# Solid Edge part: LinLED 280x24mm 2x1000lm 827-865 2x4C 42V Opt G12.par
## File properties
Author: robert.pupel
Template: iso metric part.par
Last saved by: robert.pupel
Revision: 2
Application: Solid Edge
Gęstość: 0,000 kg/m^3
Dokładność: 0,990
Username: robert.pupel
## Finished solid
Body 1: solid body, 2824 faces, 7208 edges, 4536 vertices.
  Faces by surface: plane 1666, cylinder 518, spline 384, cone 120, sphere 64, torus 40, spun 32
  Edges by curve: line 4748, curve on surface 1296, circle 684, ellipse 264, spline 200, intersection 16
Bounding box of the edges (mm; curved faces can reach further): 279.500 x 4.450 x 24.000, from (-139.75, -4.45, -12) to (139.75, 0, 12).
Cylindrical faces by radius (mm): R0.2 x184, R0.2169 x24, R0.25 x56, R0.3373 x24, R0.4 x32, R0.4006 x8, R0.4008 x8, R0.525 x8, R0.6 x80, R1 x32, R1.1 x16, R1.2 x40, R2.15 x6
Conical faces (half-angle, radius in mm at the cone's reference point): 0.5 deg R0.5056 x16, 0.5 deg R1.0082 x16, 1 deg R0.5511 x8, 10 deg R0.2132 x16, 10 deg R0.4132 x16, 18.8604 deg R1.0669 x16, 27.363 deg R0.6214 x8, 45 deg R0.575 x8, 45 deg R0.625 x16
Toroidal faces (ring radius, tube radius in mm): R0.8 r0.2 x16, R0.8522 r0.3 x8, R0.9002 r0.2 x8, R0.9018 r0.2 x8
Spherical faces by radius (mm): R0.2 x48, R0.6 x16
Planar faces by outward normal: +x 177, +y 33, +z 180, -x 177, -y 265, -z 182, oblique 652
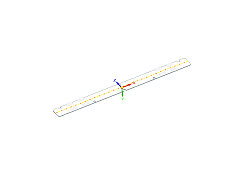
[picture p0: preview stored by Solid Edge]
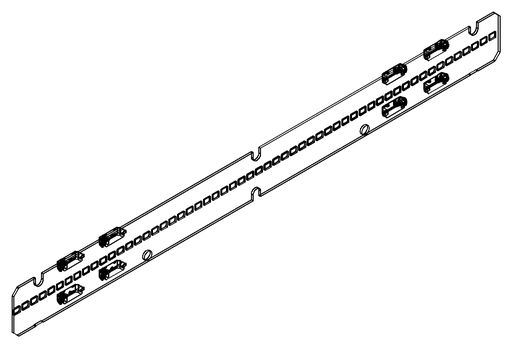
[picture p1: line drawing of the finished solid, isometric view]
